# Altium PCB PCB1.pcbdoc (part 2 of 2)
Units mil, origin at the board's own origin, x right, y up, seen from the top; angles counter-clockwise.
Board outline 2401.6 x 2401.6 mil, 2 copper layers (Top Layer, Bottom Layer), stack 62.2 mil thick; 61 components, 49 nets, 315 pads, 150 vias.
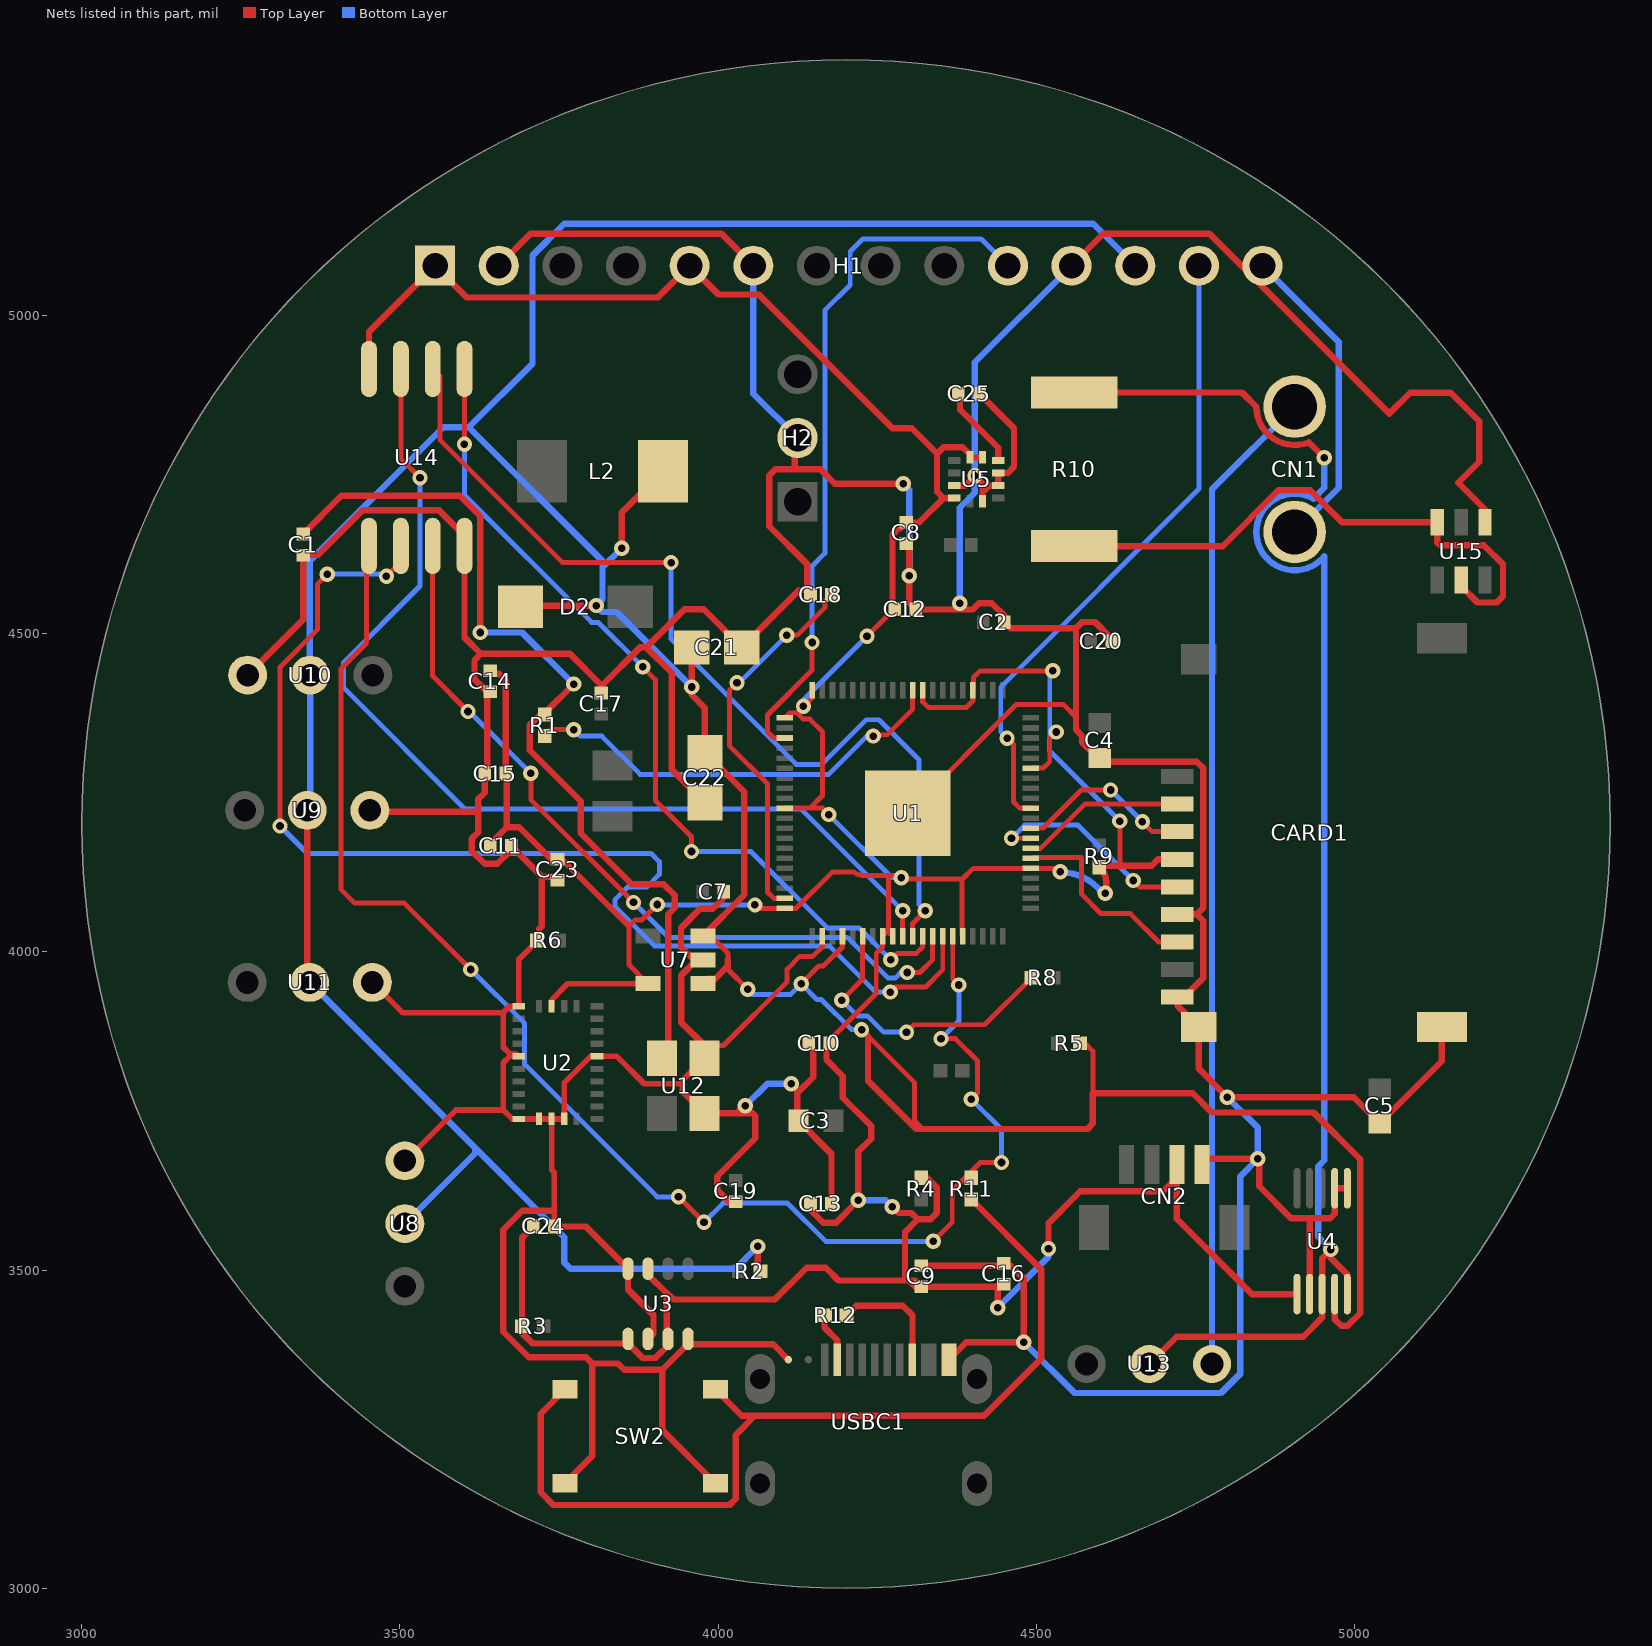
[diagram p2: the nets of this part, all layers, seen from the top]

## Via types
v1: diameter 24, hole 12, Top Layer to Bottom Layer, 150 vias

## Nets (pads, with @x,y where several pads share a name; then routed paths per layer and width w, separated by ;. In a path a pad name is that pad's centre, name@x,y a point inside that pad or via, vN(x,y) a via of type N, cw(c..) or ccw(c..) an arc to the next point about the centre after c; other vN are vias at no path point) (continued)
$1N403: H1.10 U1.43 | length 1112.8
  Top Layer w7.8: U1.43@4104.5,4335.9 4087.5,4335.9 4077.5,4345.9 4077.5,4372.1 4147.5,4442.1 v1(4147.5,4485.9)
  Bottom Layer w7.8: v1(4147.5,4485.9) 4147.5,4605.9 4167.5,4625.9 4167.5,5007.7 4207.5,5047.7 4207.5,5100.2 4227.5,5120.2 4413,5120.2 H1.10@4455.2,5078
$1N404: H1.13 U1.11 | length 1010.7
  Top Layer w7.8: v1(4453.9,4335.6) 4463.9,4325.6 4463.9,4235.6 4473.9,4225.6 U1.11@4490.9,4225.6
  Bottom Layer w7.8: v1(4453.9,4335.6) 4443.9,4345.6 4443.9,4415.6 4755.2,4727 H1.13@4755.2,5078
$1N405: CARD1.5 U1.8 | length 339.2
  Top Layer w7.8: v1(4460.9,4178.4) U1.8@4490.9,4178.4 ; v1(4652,4112.1) 4662,4102.1 CARD1.5@4721.5,4102.1
  Bottom Layer w7.8: v1(4460.9,4178.4) 4481.4,4198.9 4565.2,4198.9 v1(4652,4112.1)
$1N406: CARD1.3 U1.9 | length 282.6
  Top Layer w7.8: U1.9@4490.9,4194.2 4510.3,4194.2 4570.3,4254.2 v1(4616.5,4254.2) ; v1(4666.5,4204.2) 4682,4188.7 CARD1.3@4721.5,4188.7
  Bottom Layer w7.8: v1(4616.5,4254.2) v1(4666.5,4204.2)
$1N409: CARD1.2 U1.7 | length 259.9
  Top Layer w7.8: U1.7@4490.9,4162.7 4491.5,4162 4505.9,4162 4575.9,4232 CARD1.2@4721.5,4232
$1N413: R8.1 U1.66 | length 468.9
  Top Layer w7.8: v1(4194.1,3924.1) 4226.8,3956.8 U1.66@4226.8,4024.6 ; v1(4295.9,3873.7) 4307.5,3885.4 4418.4,3885.4 R8.1@4492.5,3959.4
  Bottom Layer w7.8: v1(4194.1,3924.1) 4218.6,3899.5 4234.4,3899.5 4260.1,3873.7 v1(4295.9,3873.7)
$1N424: R1.1 U1.30 | length 683.4
  Top Layer w7.8: R1.1@3727.6,4338.9 3737.6,4348.9 v1(3773.2,4348.9) ; v1(4243.5,4338.9) 4245.5,4341 4265.5,4341 4305.5,4381 U1.30@4305.5,4411
  Bottom Layer w7.8: v1(3773.2,4348.9) 3783.2,4338.9 3817.3,4338.9 3877.3,4278.9 4173.5,4278.9 4233.5,4338.9 v1(4243.5,4338.9)
$1N425: C1.1 R1.2 U12.1 | length 1434.9
  Top Layer w10: C1.1@3347.9,4656.4 3407.9,4716.4 3594.2,4716.4 3626.1,4684.4 v1(3626.1,4501.7) ; R1.2@3727.6,4373 R1.2@3724.2,4376.4 ; v1(3772.9,4420.6) 3728.7,4376.4 R1.2@3724.2,4376.4 ; U12.1@3911.5,3832.8 3921.5,3842.8 3921.5,4059.1 3931.5,4069.1 3931.5,4089.1 3914.2,4106.4 3864.2,4106.4 3784.2,4186.4 3784.2,4236.4 3704.2,4316.4 3704.2,4356.4 R1.2@3724.2,4376.4
  Bottom Layer w10: v1(3626.1,4501.7) 3691.9,4501.7 v1(3772.9,4420.6)
$1N433: C8.1 C9.1 C10.1 C11.1 C12.1 C13.1 C14.1 C15.1 C16.1 C23.1 C24.1 CARD1.4 CN2.2 H1.1 H1.5 R3.2 R4.2 R9.2 U1.5 U1.15 U1.24 U1.29 U1.40 U1.41 U1.50 U1.60 U1.68 U1.69 U1.76 U2.4 U3.2 U3.6 U3.8 U4.6 U5.5 U5.6 U5.10 U7.5 U14.8 | length 7842.1
  Top Layer w7.8: U7.5@3889.6,3950 3859.6,3980 3859.6,4040.3 3869.6,4050.3 3880.2,4050.3 v1(3904.3,4074.4) ; v1(4057.7,4073.7) 4063.2,4068.2 U1.60@4104.5,4068.2 4122.2,4068.2 4179.8,4125.7 4212.9,4125.7 ccw(c4226.2,4139) 4226.2,4120.2 4267,4120.2 4287.8,4120.2 v1(4287.8,4116.4) 4290,4114.3 4383.9,4114.3 ; U1.50@4104.5,4225.6 4143.9,4225.6 ; U1.41@4104.5,4367.4 4112.7,4375.6 4123.9,4375.6 ; U1.40@4148.1,4411 4148.1,4399.8 v1(4133.9,4385.6) 4123.9,4375.6 ; C10.1@4170.2,3856.4 4248.3,3934.6 4248.3,3997.6 4258.3,4007.6 U1.68@4258.3,4024.6 4264.9,4031.2 4267.5,4031.2 ; v1(4173.9,4215.6) 4163.9,4225.6 4143.9,4225.6 ; v1(4233.9,4495.6) 4273.9,4535.6 C12.1@4277.1,4538.4 ; 4267.03,4120.23 cw(c4265.9,4119.1) 4267.5,4119.1 4267.5,4031.2 ; U1.69@4274.1,4024.6 4267.5,4031.2 ; U1.29@4321.3,4411 4321.3,4392.7 4330,4384 4390,4384 4400,4394 U1.24@4400,4411 4400.9,4411.9 4400.9,4431 4410.9,4441 4450.9,4441 4451.4,4441.4 v1(4525.7,4441.4) ; U1.76@4384.3,4024.6 4382.8,4026.1 4382.8,4113.1 4383.9,4114.3 ; U1.15@4490.9,4288.6 4510.9,4288.7 4520.9,4298.7 4520.9,4335.4 v1(4530.9,4345.4) ; v1(4537.2,4125.9) 4531.9,4131.2 U1.5@4490.9,4131.2 4400.8,4131.2 4383.9,4114.3 ; 4630.9,4135.4 v1(4630.9,4205.4) ; 4123.9,4375.6 4133.9,4365.6 4143.9,4365.6 4163.9,4345.6 4163.9,4245.6 4143.9,4225.6
  Top Layer w8.9: U2.4@3738.3,3914.5 3738.3,3924.5 3763.7,3950 U7.5@3889.6,3950 ; C23.1@3747.6,4145.5 3754.4,4145.5 3859.6,4040.3
  Top Layer w9.9: C8.1@4295.8,4674.6 4315.8,4674.6 4353.9,4712.7 ; U5.10@4371.1,4712.7 4353.9,4712.7 ; U5.5@4415.4,4776.7 U5.6@4395.8,4776.7 4395.8,4780.9 4383.9,4792.7 4353.9,4792.7 4343.9,4782.7 4343.9,4722.7 4353.9,4712.7
  Top Layer w10: U14.8@3451.5,4915.7 3451.5,4974.2 H1.1@3555.2,5078 3605.2,5028 3905.2,5028 H1.5@3955.2,5078 4000.5,5032.7 4063.9,5032.7 4273.9,4822.7 4303.9,4822.7 4343.9,4782.7 ; C14.1@3641.6,4441.4 3646.2,4436.8 3656.2,4436.8 3666.2,4426.8 C15.1@3666.2,4280.1 3667.6,4278.8 3667.6,4195.5 ; C11.1@3641.7,4166.5 3641.7,4169.6 3667.6,4195.5 ; C24.1@3709.3,3568.5 3691.7,3550.9 R3.2@3691.7,3411.5 3691.7,3401.2 3708.4,3384.6 3851.1,3384.6 U3.8@3858.4,3391.8 3858.4,3384.8 3881.3,3361.8 3901.3,3361.8 3921.3,3381.8 U3.6@3921.3,3391.8 3919,3394.2 3919,3463.7 ; C23.1@3747.6,4145.5 3737.6,4145.5 3687.6,4195.5 3667.6,4195.5 ; U3.2@3889.8,3502.1 3889.8,3492.9 3919,3463.7 ; C13.1@4145,3604.5 4145,3594.5 4165,3574.5 4185,3574.5 v1(4220.2,3609.7) 4220.2,3686.4 4240.2,3706.4 4240.2,3726.4 4195.9,3770.7 4195.9,3804.6 4170.2,3830.3 C10.1@4170.2,3856.4 ; v1(4273.5,3599.7) 4283.5,3589.7 4303.5,3589.7 4313.5,3579.7 ; C12.1@4273.9,4535.6 4273.9,4655.6 4283.9,4665.6 4286.8,4665.6 C8.1@4295.8,4674.6 ; R4.2@4319,3645.1 4328.1,3645.1 4343.5,3629.7 4343.5,3589.7 4333.5,3579.7 4313.5,3579.7 ; v1(4439,3440.9) C16.1@4439,3473.7 ; C16.1@4448.9,3477.7 C16.1@4439,3473.7 ; v1(4519,3533.7) 4519,3573.7 4569,3623.7 4699,3623.7 4719,3643.7 4719,3664.4 4720.5,3666 4720.5,3580.5 4838.7,3462.3 U4.6@4909.5,3462.3 ; R9.2@4598.8,4132.9 4601.2,4135.4 4630.9,4135.4 4680.9,4135.4 4690.9,4145.4 CARD1.4@4721.5,4145.4 ; R9.2@4600.76,4131.26 cw(c4579.9,4110.4) 4609.4,4110.4 v1@4609.4,4093.6 ; 3919,3463.7 3920.2,3463.7 3930.2,3453.7 4089,3453.7 4139,3503.7 4169,3503.7 4189,3483.7 4299.4,3483.7 ; 4299.4,3483.7 4293.5,3489.7 4293.5,3559.7 4313.5,3579.7 ; 4299.4,3483.7 4309.4,3473.7 C9.1@4319,3473.7 ; 4299.4,3483.7 4309,3483.7 C9.1@4319,3473.7 ; C9.1@4319,3473.7 C16.1@4439,3473.7
  Bottom Layer w7.8: v1(3904.3,4074.4) 3905.1,4073.7 v1(4057.7,4073.7) ; v1(4133.9,4385.6) 4133.9,4395.6 v1(4233.9,4495.6) ; v1(4173.9,4215.6) 4273.1,4116.4 v1(4287.8,4116.4) ; v1(4525.7,4441.4) 4520.9,4436.7 4520.9,4335.4 ; v1(4530.9,4345.4) 4520.9,4335.4 ; v1(4630.9,4205.4) 4520.9,4315.4 4520.9,4335.4
  Bottom Layer w10: v1(4220.2,3609.7) 4263.5,3609.7 v1(4273.5,3599.7) ; v1(4439,3440.9) 4519,3520.9 v1(4519,3533.7) ; v1@4536.4,4124.8 v1@4539,4124.8 ; v1@4539,4124.9 cw(c4539,4045.3) v1@4606.65,4087.25
  other v1: 4608.3,4092.2
$1N438: R11.1 U1.75 U14.1 | length 2399.5
  Top Layer w7.8: U14.1@3451.5,4637.7 3447.7,4634 3447.7,4485.1 3407.7,4445.1 3407.7,4097.6 3428.8,4076.5 3507,4076.5 v1(3611.3,3972.2) ; v1(3937.7,3615.1) v1(3977.7,3575.1) ; v1(4337.7,3545.1) 4367.7,3575.1 4367.7,3625.1 4411.6,3669 v1(4445,3669) ; v1(4350.1,3863.5) 4372.7,3863.5 4407.7,3828.4 4407.7,3778.4 v1(4397.7,3768.4) ; U1.75@4368.5,4024.6 4368.5,3957.4 v1(4378,3947.9)
  Bottom Layer w7.8: v1(3611.3,3972.2) 3695.9,3887.6 3695.9,3823.2 3904,3615.1 v1(3937.7,3615.1) ; v1(3977.7,3575.1) 4007.7,3605.1 4109,3605.1 4169,3545.1 v1(4337.7,3545.1) ; v1(4350.1,3863.5) 4378,3891.3 v1(4378,3947.9) ; v1(4397.7,3768.4) 4445,3721.1 v1(4445,3669)
$1N439: R11.2 SW2.1 SW2.2 | length 1501.4
  Top Layer w10: SW2.1@3759.4,3312.7 3721,3274.3 3721,3151 3741,3131 4017.7,3131 4027.7,3141 4027.7,3241 4057.7,3271 ; SW2.2@3995.6,3312.7 4037.2,3271 4417.7,3271 4507.7,3361 4507.7,3501 R11.2@4397.7,3611
$1N444: C18.1 U1.59 | length 601.4
  Top Layer w7.8: v1(4029.6,4422.7) 4017.5,4410.6 4017.5,4323.9 4077.5,4263.9 4077.5,4093.9 4087.5,4083.9 U1.59@4104.5,4083.9 ; v1(4107.5,4497.4) 4124.2,4497.4 4167.5,4540.6 4167.5,4550.6 C18.1@4178,4561.1
  Bottom Layer w7.8: v1(4029.6,4422.7) 4032.9,4422.7 v1(4107.5,4497.4)
$1N449: U1.74 U14.2 | length 1951.9
  Top Layer w7.8: v1(3311.5,4197.7) 3311.5,4447.3 3370.2,4506 3370.2,4577.3 v1(3386,4593.2) ; v1(3478.8,4590.1) 3501.5,4612.8 U14.2@3501.5,4637.7 ; v1(4270.2,3936.7) 4278.1,3944.5 4325.8,3944.5 4352.8,3971.6 U1.74@4352.8,4024.6
  Bottom Layer w7.8: v1(3311.5,4197.7) 3354.7,4154.5 3894.7,4154.5 3907.6,4141.6 3907.6,4121.6 3887.6,4101.6 3857.6,4101.6 3837.6,4081.6 3837.6,4071.6 3900.3,4008.9 4175.5,4008.9 4247.7,3936.7 v1(4270.2,3936.7) ; v1(3386,4593.2) 3475.7,4593.2 v1(3478.8,4590.1)
$1N450: U1.73 U14.3 | length 1260.1
  Top Layer w7.8: U14.3@3551.5,4637.7 3551.5,4433.2 v1(3607,4377.6) ; v1(3705.7,4280.5) 3705.7,4238.9 v1(3867,4077.6) ; v1(4297,3967.6) 4317,3967.6 4337,3987.6 U1.73@4337,4024.6
  Bottom Layer w7.8: v1(3607,4377.6) 3608.7,4377.6 v1(3705.7,4280.5) ; v1(3867,4077.6) 3922,4022.7 4203,4022.7 4267,3958.6 4278.1,3958.6 4287,3967.6 v1(4297,3967.6)
$1N451: U1.72 U14.5 | length 1370.5
  Top Layer w7.8: v1(3601.3,4797.6) U14.5@3601.3,4915.5 ; v1(3881.3,4447.6) 3901.3,4427.6 3901.3,4237.6 3958,4180.9 v1(3958,4157.6) ; v1(4271.3,3987.6) 4281.3,3997.6 4311.3,3997.6 4321.3,4007.6 U1.72@4321.3,4024.6
  Bottom Layer w7.8: v1(3601.3,4797.6) 3601.3,4717.6 3801.3,4517.6 3811.3,4517.6 v1(3881.3,4447.6) ; v1(3958,4157.6) 4051.3,4157.6 4171.3,4037.6 4221.3,4037.6 v1(4271.3,3987.6)
$1N452: U1.71 U14.6 | length 1494.9
  Top Layer w7.8: U14.6@3551.5,4915.7 3562.6,4904.6 3562.6,4804.6 3755.7,4611.5 v1(3926,4611.5) ; U1.71@4305.5,4024.6 4305.5,4044.6 v1(4325.5,4064.6)
  Bottom Layer w7.8: v1(3926,4611.5) 3926,4491.2 4122.6,4294.6 4162.6,4294.6 4232.6,4364.6 4252.6,4364.6 4315.5,4301.6 4315.5,4074.6 v1(4325.5,4064.6)
$1N453: U1.70 U14.7 | length 1626.5
  Top Layer w7.8: U14.7@3501.5,4915.7 3501.5,4774.6 v1(3531.5,4744.6) ; U1.70@4289.8,4024.6 v1(4289.8,4064.6)
  Bottom Layer w7.8: v1(3531.5,4744.6) 3531.5,4574.6 3411.5,4454.6 3411.5,4414.6 3601.5,4224.6 4129.8,4224.6 v1(4289.8,4064.6)
$1N456: C25.1 U5.4 | length 131.1
  Top Layer w9.9: C25.1@4377.5,4877 4380,4874.5 4380,4851.8 4440,4791.8 U5.4@4440,4771.8
$1N460: CARD1.7 U1.6 | length 319.9
  Top Layer w7.8: U1.6@4490.9,4146.9 4494.8,4146.9 4496.1,4148.2 4570.9,4148.2 4570.9,4090.5 4601.5,4060 4647.5,4060 4692,4015.5 CARD1.7@4721.5,4015.5
$1N462: R10.1 U4.8 U4.10 U13.2 | length 2388.2
  Top Layer w10: R10.1@4559.5,4878.8 4823,4878.8 4845.4,4856.4 ccw(c4905.6,4856.4) 4927.76,4800.43 ; U13.2@4677.2,3352.5 4720.2,3395.4 4918.9,3395.4 4948.9,3425.4 U4.8@4948.9,3462.3 4948.9,3518.8 v1(4962.4,3532.3) 4962.4,3518.9 4988.3,3493 U4.10@4988.3,3462.3 ; 4927.7,4800.4 v1(4952.2,4776)
  Bottom Layer w10: 4935.3,4711.9 4952.2,4728.8 v1(4952.2,4776) ; 4935.34,4711.94 ccw(c4905.6,4659.6) 4845.4,4659.6 ccw(c4905.6,4659.6) 4952.19,4621.47 ; 4952.2,4621.5 4952.2,3672.4 4942.5,3662.7 4942.5,3552.2 v1(4962.4,3532.3)
$1N464: CN1.2 U13.1 | length 1557.7
  Bottom Layer w10: U13.1@4775.7,3352.5 4775.7,4726.5 CN1.2@4905.6,4856.4
$1N465: C1.2 C2.2 C3.2 C4.2 C5.2 C7.2 C8.2 C9.2 C10.2 C11.2 C12.2 C13.2 C14.2 C15.2 C16.2 C17.2 C18.2 C19.2 C20.2 C21.2 C22.2 C23.2 C24.2 C25.2 CARD1.6 CARD1.9 CARD1.10 CARD1.11 CN1.1 CN2.1 H1.2 H1.6 H1.11 H1.14 H2.2 R6.2 SW2.3 SW2.4 U1.62 U1.81 U2.6 U2.10 U2.15 U2.16 U2.17 U2.18 U2.25 U3.1 U3.5 U3.7 U4.1 U4.2 U4.7 U5.2 U5.3 U5.9 U5.12 U7.2 U8.3 U9.3 U10.3 U11.3 U12.3 U12.4 U14.4 U15.1 USBC1.A1B12 USBC1.B1A12 | length 14395.4
  Top Layer w7.8: U12.4@3978.4,3852.8 4008.4,3852.8 4108.4,3952.8 4108.4,3972.8 4128.4,3992.8 4148.4,3992.8 4163.8,4008.2 U1.62@4163.8,4024.6 ; U1.81@4297.7,4217.8 4468.7,4388.8 4542.1,4388.8 4562.1,4368.8
  Top Layer w8.9: U11.3@3456.8,3951.8 3504.1,3904.5 3662.3,3904.5 ; U8.3@3507.8,3671.4 3588.1,3751.6 3662.3,3751.6 ; 3718.8,4036.2 3718.8,4020 3686.6,3987.8 U2.6@3686.6,3914.5 3672.3,3914.5 3662.3,3904.5 ; C24.2@3742.4,3568.5 3742.4,3653.3 3738.3,3657.4 U2.17@3738.3,3737.4 ; U12.4@3978.4,3832.8 3943.9,3798.3 3943.9,3792.8 3883.9,3792.8 3840.9,3835.8 U2.25@3809.6,3835.8 3799.6,3835.8 3758,3794.1 U2.18@3758,3737.4 U2.17@3738.3,3737.4 ; 3662.3,3751.6 3662.3,3825.8 3672.3,3835.8 U2.10@3686.6,3835.8 3682.3,3840 3672.3,3840 3662.3,3850 3662.3,3904.5 ; 3662.3,3751.6 3676.6,3737.4 U2.15@3686.6,3737.4 U2.16@3718.6,3737.4 U2.17@3738.3,3737.4
  Top Layer w9.9: U5.9@4371.1,4732.4 4388,4732.4 v1(4403.3,4747.7) 4415.4,4735.5 4415.4,4722.1 ; v1@4379.7,4537.8 v1(4379.7,4547.8) ; C25.2@4410.6,4877 4464.8,4822.8 4464.8,4762.1 4454.8,4752.1 U5.3@4440,4752.1 U5.2@4440,4732.4 4425.7,4732.4 4415.4,4722.1 ; U5.12@4415.4,4707.8 4415.4,4722.1
  Top Layer w10: U10.3@3260.7,4434.8 3347.9,4522 C1.2@3347.9,4623.3 3348.4,4623.9 3371.5,4623.9 3441.5,4693.8 3561.5,4693.8 3601.5,4653.8 U14.4@3601.5,4633.9 ; U9.3@3452.8,4222.1 3454.7,4220.1 3623.1,4220.1 ; U14.4@3601.5,4637.7 3601.5,4493.9 3627.1,4468.2 ; C14.2@3641.6,4408.3 C14.2@3637.1,4408.2 ; H1.2@3655.2,5078 3705.2,5128 4005.2,5128 H1.6@4055.2,5078 ; C11.2@3674.8,4166.5 C11.2@3673.1,4158.1 ; 3718.8,4036.2 3723.1,4040.5 3723.1,4118.1 ; C24.2@3742.4,3568.5 3792,3568.5 U3.1@3858.4,3502.1 3858.4,3469.4 3898.4,3429.4 3898.4,3400.4 U3.7@3889.8,3391.8 ; 3742.4,3593.3 3692.4,3593.3 3662.4,3563.3 3662.4,3403.3 3702.4,3363.3 3792.4,3363.3 3802.4,3353.3 ; C23.2@3747.6,4112.4 3742,4118.1 3723.1,4118.1 ; SW2.3@3759.4,3165 3802.4,3208 3802.4,3353.3 ; C17.2@3816.6,4406.6 3817.1,4418.2 ; 3943.9,3792.8 3943.9,3780.7 U12.3@3978.4,3746.2 4028.4,3746.2 ; U3.5@3952.8,3391.8 U3.5@3952.4,3383.3 ; U12.4@3978.4,3832.8 3978.4,3852.8 3941.7,3889.6 3941.7,3962.8 3966.2,3987.4 U7.2@3976.2,3987.4 3961.5,3987.4 3941.5,4007.4 3941.5,4037.4 3971.5,4067.4 3991.5,4067.4 4008.9,4084.7 C7.2@4008.9,4094.7 ; C22.2@3979.1,4234.4 3927.1,4286.4 3927.1,4438.2 3887.1,4478.2 ; SW2.4@3995.6,3165 3912.4,3248.3 3912.4,3343.3 ; C19.2@4027.6,3607.6 4017,3607.6 3998.4,3626.2 3998.4,3647.5 4058.3,3707.3 4058.3,3742.3 4054.4,3746.2 4028.4,3746.2 ; v1(4042.4,3758) 4040.2,3758 4028.4,3746.2 ; USBC1.A1B12@4110.3,3359.3 4086.4,3383.3 U3.5@3952.4,3383.3 ; v1(4114.8,3792.9) 4124.3,3783.4 4124.3,3778.2 ; H2.2@4124.8,4807.4 4120.2,4802.8 4120.2,4758.4 ; C10.2@4137.1,3856.4 4149.3,3844.2 4149.3,3803.2 4124.3,3778.2 ; C18.2@4145,4561.1 C18.2@4140.2,4568.4 ; C13.2@4178,3604.5 4178,3682.4 C3.2@4126.1,3734.4 4124.3,3736.2 4124.3,3778.2 ; v1(4290.6,4735.5) 4183.1,4735.5 4160.2,4758.4 4120.2,4758.4 ; C8.2@4295.8,4641.5 4300.2,4637.1 v1(4300.2,4590.8) 4300.2,4548.4 C12.2@4310.2,4538.4 4310.8,4537.8 4399.7,4537.8 4409.7,4547.8 4429.7,4547.8 4449.7,4527.8 C2.2@4449.7,4517.8 4459.3,4508.2 4562.1,4508.2 ; C9.2@4319,3506.8 4459.9,3506.8 4479.9,3486.8 v1(4479.9,3386.8) 4389.8,3386.8 USBC1.B1A12@4362.3,3359.3 ; C16.2@4448.9,3510.8 C16.2@4449.9,3506.8 ; H1.11@4555.2,5078 4605.2,5128 4771.8,5128 5054.2,4845.6 5087.1,4878.5 5150.8,4878.5 5195.8,4833.5 5195.8,4769.8 5162.9,4736.9 5205.2,4694.6 5205.2,4675.4 U15.1@5204.7,4674.9 ; C4.2@4599.8,4304.6 4605.6,4298.8 4752.1,4298.8 4762.1,4288.8 4762.1,4068.8 4752.1,4058.8 ; C4.2@4612.1,4298.8 4602.1,4298.8 4572.1,4328.8 4572.1,4338.8 4562.1,4348.8 4562.1,4508.2 ; C20.2@4618.5,4488.2 4618.5,4491.8 4592.1,4518.2 4572.1,4518.2 4562.1,4508.2 ; CARD1.6@4721.5,4058.8 4752.1,4058.8 ; CN2.1@4759.9,3666 4768.7,3674.7 v1(4847.7,3674.7) 4849.9,3672.5 4849.9,3631.6 4899.9,3581.6 4961.7,3581.6 4968.6,3588.5 U4.2@4968.6,3628.5 U4.1@4988.3,3628.5 ; U4.7@4929.2,3462.3 4929.2,3579.1 4931.7,3581.6 ; CARD1.11@5136.9,3881.6 5136.9,3827.9 5039.5,3730.4 4998.3,3771.6 v1(4799.9,3771.6) 4755,3816.6 CARD1.10@4755,3881.6 4721.5,3915.1 CARD1.9@4721.5,3928.9 4732.2,3928.9 4762.1,3958.8 4762.1,4048.8 4752.1,4058.8 ; 3627.1,4468.2 3767.1,4468.2 3817.1,4418.2 ; 3627.1,4468.2 3617.1,4458.2 3617.1,4428.2 C14.2@3637.1,4408.2 ; C14.2@3637.1,4408.2 3637.1,4284.1 C15.2@3633.1,4280.1 3633.1,4250.1 3623.1,4240.1 3623.1,4188.1 3613.1,4178.1 3613.1,4158.1 3633.1,4138.1 3653.1,4138.1 C11.2@3673.1,4158.1 ; C11.2@3673.1,4158.1 3683.1,4158.1 3723.1,4118.1 ; 3802.4,3353.3 3842.4,3353.3 3852.4,3343.3 3912.4,3343.3 ; 3817.1,4418.2 3877.1,4478.2 3887.1,4478.2 ; 3887.1,4478.2 3947.1,4538.2 3977.1,4538.2 C21.2@4037.1,4478.2 4127.3,4568.4 C18.2@4140.2,4568.4 ; 3912.4,3343.3 U3.5@3952.4,3383.3 ; 4120.2,4758.4 4090.2,4758.4 4080.2,4748.4 4080.2,4668.4 4140.2,4608.4 C18.2@4140.2,4568.4
  Bottom Layer w9.9: v1(4379.7,4547.8) 4379.7,4697.8 4403.3,4721.4 v1(4403.3,4747.7)
  Bottom Layer w10: v1(4042.4,3758) 4077.4,3792.9 v1(4114.8,3792.9) ; H1.6@4055.2,5078 4055.2,4876.9 H2.2@4124.8,4807.4 ; v1(4290.6,4735.5) 4300.2,4725.9 v1(4300.2,4590.8) ; v1(4403.3,4747.7) 4403.3,4926 H1.11@4555.2,5078 ; v1(4479.9,3386.8) 4559.9,3306.8 4789.9,3306.8 4819.9,3336.8 4819.9,3647 v1(4847.7,3674.7) 4847.7,3723.9 v1(4799.9,3771.6) ; H1.14@4855.2,5078 4975.2,4958 4975.2,4729.2 CN1.1@4905.6,4659.6
$1N470: R10.2 U15.3 U15.5 | length 916.8
  Top Layer w10: R10.2@4559.5,4637.4 4792.5,4637.4 4880,4724.9 4930,4724.9 4980,4674.9 U15.3@5129.9,4674.9 5129.9,4642.9 5134.1,4638.8 5202.9,4638.8 5232.9,4608.8 5232.9,4558.8 5222.9,4548.8 5192.9,4548.8 5167.3,4574.4 U15.5@5167.3,4584.4
$1N471: C21.1 C22.1 D2.1 H1.12 L2.2 R2.2 R5.1 U1.64 U4.9 U7.1 U7.3 U8.2 U9.2 U10.2 U11.2 | length 6928.5
  Top Layer w7.8: U7.3@3976.2,4024.8 3988.1,4024.8 4015.3,3997.6 4015.3,3987.6 ; 4015.3,3977.6 4015.3,3972.2 v1(4046.4,3941.2) ; v1(4130.3,3949.7) 4158.2,3977.6 4165.3,3977.6 4195.3,4007.6 U1.64@4195.3,4024.6 ; v1(4225.3,3877.6) 4308.6,3794.3 4308.6,3734.3 4321.3,3721.6 4321.6,3721.3 ; R5.1@4568.3,3856.4 4576.2,3856.4 4588.6,3844 4588.6,3777.6
  Top Layer w10: U9.2@3354.4,4222.1 3354.4,3955.8 U11.2@3358.4,3951.8 ; D2.1@3689.2,4541.9 3691.2,4543.9 v1(3808.3,4543.9) ; v1(3848.3,4633.9) 3848.3,4690.1 L2.2@3913.1,4754.8 ; C21.1@3958.3,4478.2 v1(3958.3,4416) 3958.3,4403.9 3979.1,4383.1 C22.1@3979.1,4313.1 4040.9,4251.3 4040.9,4089.5 U7.3@3976.2,4024.8 ; U7.1@3976.2,3950 3983.8,3957.6 3995.3,3957.6 4015.3,3977.6 4015.3,3987.6 ; v1(4062.3,3537.2) 4062.3,3502.6 R2.2@4066.7,3498.2 ; 4235.3,3867.6 4235.3,3797.6 4311.3,3721.6 4321.3,3721.6 4580.1,3721.6 4588.6,3730.2 4588.6,3777.6 4745.3,3777.6 4775.3,3747.6 4935.3,3747.6 5008.6,3674.3 5008.6,3432.3 4988.6,3412.3 4978.6,3412.3 4968.6,3422.3 U4.9@4968.6,3462.3
  Bottom Layer w7.8: v1(4046.4,3941.2) 4054.8,3932.7 4113.4,3932.7 v1(4130.3,3949.7) 4155.2,3924.8 4162.3,3924.8 4209.6,3877.6 v1(4225.3,3877.6)
  Bottom Layer w10: U9.2@3354.4,4222.1 3359.1,4226.7 U10.2@3359.1,4434.8 3358.3,4435.6 3358.3,4613.9 3568.3,4823.9 3608.3,4823.9 ; U11.2@3358.4,3951.8 3581.1,3729.1 3758.4,3551.8 3758.4,3511.8 3768.4,3501.8 4026.9,3501.8 v1(4062.3,3537.2) ; U8.2@3507.8,3573 3618.4,3683.5 3618.4,3691.8 ; v1(3848.3,4633.9) 3818.3,4603.9 ; v1(3958.3,4416) 3840.5,4533.9 3818.3,4533.9 v1(3808.3,4543.9) 3818.3,4553.9 3818.3,4603.9 ; H1.12@4655.2,5078 4589.3,5143.9 3758.3,5143.9 3708.3,5093.9 3708.3,4923.9 3608.3,4823.9 ; 3608.3,4823.9 3818.3,4613.9 3818.3,4603.9
$1N472: R12.2 USBC1.B5 | length 185.3
  Top Layer w10: R12.2@4201.8,3429.1 4216.7,3443.9 4290.1,3443.9 4305.2,3428.9 USBC1.B5@4305.2,3359.3
$1N473: R12.1 USBC1.A5 | length 78.3
  Top Layer w10: R12.1@4167.7,3429.1 4167.1,3428.4 4167.1,3409.9 4187.1,3389.9 USBC1.A5@4187.1,3359.3
pads on no net: CARD1.1 CARD1.8 CARD1.12 CARD1.13 CN2.0 U1.3 U1.4 U1.12 U1.13 U1.14 U1.16 U1.17 U1.18 U1.19 U1.20 U1.21 U1.22 U1.23 U1.25 U1.26 U1.27 U1.28 U1.35 U1.36 U1.37 U1.38 U1.39 U1.42 U1.47 U1.48 U1.49 U1.52 U1.53 U1.54 U1.55 U1.56 U1.57 U1.58 U2.1 U2.2 U2.3 U2.5 U2.7 U2.8 U2.9 U2.12 U2.13 U2.14 U2.21 U2.22 U2.23 U2.24 U2.26 U2.27 U2.28 U4.3 U5.7 U5.8 U7.4 U13.3 USBC1.1 USBC1.2 USBC1.3 USBC1.4 USBC1.A8 USBC1.B6 USBC1.B7 USBC1.B8

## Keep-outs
Board Outline Layer:
  region: 3348,4782.3 3347.6,4775.5 3346.5,4768.7 3344.5,4762.1 3341.9,4755.8 3338.5,4749.8 3334.5,4744.3 3329.8,4739.3 3324.7,4734.8 3319,4730.9 3312.9,4727.7 3306.5,4725.2 3299.9,4723.5 3293.1,4722.5 3286.3,4722.3 3279.4,4722.9 3272.7,4724.2 3266.2,4726.4 3260,4729.2 3254.1,4732.7 3248.7,4736.9 3243.8,4741.7 3239.4,4747 3235.7,4752.8 3232.7,4758.9 3230.4,4765.4 3228.8,4772.1 3228,4778.9 3228,4785.7 3228.8,4792.5 3230.4,4799.2 3232.7,4805.7 3235.7,4811.8 3239.4,4817.6 3243.8,4822.9 3248.7,4827.7 3254.1,4831.9 3260,4835.4 3266.2,4838.3 3272.7,4840.4 3279.4,4841.7 3286.3,4842.3 3293.1,4842.1 3299.9,4841.2 3306.5,4839.4 3312.9,4836.9 3319,4833.7 3324.7,4829.9 3329.8,4825.4 3334.5,4820.3 3338.5,4814.8 3341.9,4808.8 3344.5,4802.5 3346.5,4795.9 3347.6,4789.2
  region: 3348,4782.3 3347.6,4775.5 3346.5,4768.7 3344.5,4762.1 3341.9,4755.8 3338.5,4749.8 3334.5,4744.3 3329.8,4739.3 3324.7,4734.8 3319,4730.9 3312.9,4727.7 3306.5,4725.2 3299.9,4723.5 3293.1,4722.5 3286.3,4722.3 3279.4,4722.9 3272.7,4724.2 3266.2,4726.4 3260,4729.2 3254.1,4732.7 3248.7,4736.9 3243.8,4741.7 3239.4,4747 3235.7,4752.8 3232.7,4758.9 3230.4,4765.4 3228.8,4772.1 3228,4778.9 3228,4785.7 3228.8,4792.5 3230.4,4799.2 3232.7,4805.7 3235.7,4811.8 3239.4,4817.6 3243.8,4822.9 3248.7,4827.7 3254.1,4831.9 3260,4835.4 3266.2,4838.3 3272.7,4840.4 3279.4,4841.7 3286.3,4842.3 3293.1,4842.1 3299.9,4841.2 3306.5,4839.4 3312.9,4836.9 3319,4833.7 3324.7,4829.9 3329.8,4825.4 3334.5,4820.3 3338.5,4814.8 3341.9,4808.8 3344.5,4802.5 3346.5,4795.9 3347.6,4789.2
  region: 5179,4801.7 5178.6,4794.8 5177.4,4788.1 5175.5,4781.5 5172.8,4775.2 5169.4,4769.2 5165.4,4763.7 5160.8,4758.6 5155.6,4754.1 5149.9,4750.2 5143.9,4747 5137.5,4744.6 5130.9,4742.8 5124.1,4741.8 5117.2,4741.6 5110.4,4742.2 5103.7,4743.6 5097.2,4745.7 5090.9,4748.6 5085,4752.1 5079.6,4756.3 5074.7,4761.1 5070.4,4766.4 5066.7,4772.1 5063.6,4778.3 5061.3,4784.7 5059.8,4791.4 5059,4798.2 5059,4805.1 5059.8,4811.9 5061.3,4818.6 5063.6,4825 5066.7,4831.2 5070.4,4837 5074.7,4842.3 5079.6,4847 5085,4851.2 5090.9,4854.8 5097.2,4857.6 5103.7,4859.7 5110.4,4861.1 5117.2,4861.7 5124.1,4861.5 5130.9,4860.5 5137.5,4858.8 5143.9,4856.3 5149.9,4853.1 5155.6,4849.2 5160.8,4844.7 5165.4,4839.7 5169.4,4834.1 5172.8,4828.2 5175.5,4821.8 5177.4,4815.3 5178.6,4808.5
  region: 5179,4801.7 5178.6,4794.8 5177.4,4788.1 5175.5,4781.5 5172.8,4775.2 5169.4,4769.2 5165.4,4763.7 5160.8,4758.6 5155.6,4754.1 5149.9,4750.2 5143.9,4747 5137.5,4744.6 5130.9,4742.8 5124.1,4741.8 5117.2,4741.6 5110.4,4742.2 5103.7,4743.6 5097.2,4745.7 5090.9,4748.6 5085,4752.1 5079.6,4756.3 5074.7,4761.1 5070.4,4766.4 5066.7,4772.1 5063.6,4778.3 5061.3,4784.7 5059.8,4791.4 5059,4798.2 5059,4805.1 5059.8,4811.9 5061.3,4818.6 5063.6,4825 5066.7,4831.2 5070.4,4837 5074.7,4842.3 5079.6,4847 5085,4851.2 5090.9,4854.8 5097.2,4857.6 5103.7,4859.7 5110.4,4861.1 5117.2,4861.7 5124.1,4861.5 5130.9,4860.5 5137.5,4858.8 5143.9,4856.3 5149.9,4853.1 5155.6,4849.2 5160.8,4844.7 5165.4,4839.7 5169.4,4834.1 5172.8,4828.2 5175.5,4821.8 5177.4,4815.3 5178.6,4808.5
  region: 3356.3,3622.1 3355.9,3615.3 3354.7,3608.5 3352.8,3601.9 3350.1,3595.6 3346.7,3589.7 3342.7,3584.1 3338.1,3579.1 3332.9,3574.6 3327.2,3570.7 3321.2,3567.5 3314.8,3565 3308.1,3563.3 3301.4,3562.3 3294.5,3562.1 3287.7,3562.7 3281,3564.1 3274.4,3566.2 3268.2,3569 3262.3,3572.6 3256.9,3576.7 3252,3581.5 3247.6,3586.8 3243.9,3592.6 3240.9,3598.7 3238.6,3605.2 3237.1,3611.9 3236.3,3618.7 3236.3,3625.5 3237.1,3632.4 3238.6,3639 3240.9,3645.5 3243.9,3651.6 3247.6,3657.4 3252,3662.7 3256.9,3667.5 3262.3,3671.7 3268.2,3675.2 3274.4,3678.1 3281,3680.2 3287.7,3681.6 3294.5,3682.1 3301.4,3681.9 3308.1,3681 3314.8,3679.2 3321.2,3676.7 3327.2,3673.5 3332.9,3669.7 3338.1,3665.2 3342.7,3660.1 3346.7,3654.6 3350.1,3648.6 3352.8,3642.3 3354.7,3635.7 3355.9,3629
  region: 3356.3,3622.1 3355.9,3615.3 3354.7,3608.5 3352.8,3601.9 3350.1,3595.6 3346.7,3589.7 3342.7,3584.1 3338.1,3579.1 3332.9,3574.6 3327.2,3570.7 3321.2,3567.5 3314.8,3565 3308.1,3563.3 3301.4,3562.3 3294.5,3562.1 3287.7,3562.7 3281,3564.1 3274.4,3566.2 3268.2,3569 3262.3,3572.6 3256.9,3576.7 3252,3581.5 3247.6,3586.8 3243.9,3592.6 3240.9,3598.7 3238.6,3605.2 3237.1,3611.9 3236.3,3618.7 3236.3,3625.5 3237.1,3632.4 3238.6,3639 3240.9,3645.5 3243.9,3651.6 3247.6,3657.4 3252,3662.7 3256.9,3667.5 3262.3,3671.7 3268.2,3675.2 3274.4,3678.1 3281,3680.2 3287.7,3681.6 3294.5,3682.1 3301.4,3681.9 3308.1,3681 3314.8,3679.2 3321.2,3676.7 3327.2,3673.5 3332.9,3669.7 3338.1,3665.2 3342.7,3660.1 3346.7,3654.6 3350.1,3648.6 3352.8,3642.3 3354.7,3635.7 3355.9,3629
  region: 5187.2,3641.5 5186.8,3634.6 5185.6,3627.9 5183.7,3621.3 5181,3615 5177.7,3609 5173.6,3603.5 5169,3598.4 5163.8,3593.9 5158.2,3590.1 5152.1,3586.9 5145.7,3584.4 5139.1,3582.6 5132.3,3581.6 5125.4,3581.5 5118.6,3582 5111.9,3583.4 5105.4,3585.5 5099.1,3588.4 5093.3,3591.9 5087.8,3596.1 5082.9,3600.9 5078.6,3606.2 5074.9,3611.9 5071.9,3618.1 5069.6,3624.6 5068,3631.2 5067.2,3638 5067.2,3644.9 5068,3651.7 5069.6,3658.4 5071.9,3664.8 5074.9,3671 5078.6,3676.8 5082.9,3682.1 5087.8,3686.8 5093.3,3691 5099.1,3694.6 5105.4,3697.4 5111.9,3699.5 5118.6,3700.9 5125.4,3701.5 5132.3,3701.3 5139.1,3700.3 5145.7,3698.6 5152.1,3696.1 5158.2,3692.9 5163.8,3689 5169,3684.5 5173.6,3679.5 5177.7,3673.9 5181,3668 5183.7,3661.6 5185.6,3655.1 5186.8,3648.3
  region: 5187.2,3641.5 5186.8,3634.6 5185.6,3627.9 5183.7,3621.3 5181,3615 5177.7,3609 5173.6,3603.5 5169,3598.4 5163.8,3593.9 5158.2,3590.1 5152.1,3586.9 5145.7,3584.4 5139.1,3582.6 5132.3,3581.6 5125.4,3581.5 5118.6,3582 5111.9,3583.4 5105.4,3585.5 5099.1,3588.4 5093.3,3591.9 5087.8,3596.1 5082.9,3600.9 5078.6,3606.2 5074.9,3611.9 5071.9,3618.1 5069.6,3624.6 5068,3631.2 5067.2,3638 5067.2,3644.9 5068,3651.7 5069.6,3658.4 5071.9,3664.8 5074.9,3671 5078.6,3676.8 5082.9,3682.1 5087.8,3686.8 5093.3,3691 5099.1,3694.6 5105.4,3697.4 5111.9,3699.5 5118.6,3700.9 5125.4,3701.5 5132.3,3701.3 5139.1,3700.3 5145.7,3698.6 5152.1,3696.1 5158.2,3692.9 5163.8,3689 5169,3684.5 5173.6,3679.5 5177.7,3673.9 5181,3668 5183.7,3661.6 5185.6,3655.1 5186.8,3648.3
  lines w0.1: 3228,4778.9 3228.8,4772.1 3230.4,4765.4 3232.7,4758.9 3235.7,4752.8 3239.4,4747 3243.8,4741.7 3248.7,4736.9 3254.1,4732.7 3260,4729.2 3266.2,4726.4 3272.7,4724.2 3279.4,4722.9 3286.3,4722.3 3293.1,4722.5 3299.9,4723.5 3306.5,4725.2 3312.9,4727.7 3319,4730.9 3324.7,4734.8 3329.8,4739.3 3334.5,4744.3 3338.5,4749.8 3341.9,4755.8 3344.5,4762.1 3346.5,4768.7 3347.6,4775.5 3348,4782.3 3347.6,4789.2 3346.5,4795.9 3344.5,4802.5 3341.9,4808.8 3338.5,4814.8 3334.5,4820.3 3329.8,4825.4 3324.7,4829.9 3319,4833.7 3312.9,4836.9 3306.5,4839.4 3299.9,4841.2 3293.1,4842.1 3286.3,4842.3 3279.4,4841.7 3272.7,4840.4 3266.2,4838.3 3260,4835.4 3254.1,4831.9 3248.7,4827.7 3243.8,4822.9 3239.4,4817.6 3235.7,4811.8 3232.7,4805.7 3230.4,4799.2 3228.8,4792.5 3228,4785.7 3228,4778.9 ; 3236.3,3618.7 3237.1,3611.9 3238.6,3605.2 3240.9,3598.7 3243.9,3592.6 3247.6,3586.8 3252,3581.5 3256.9,3576.7 3262.3,3572.6 3268.2,3569 3274.4,3566.2 3281,3564.1 3287.7,3562.7 3294.5,3562.1 3301.4,3562.3 3308.1,3563.3 3314.8,3565 3321.2,3567.5 3327.2,3570.7 3332.9,3574.6 3338.1,3579.1 3342.7,3584.1 3346.7,3589.7 3350.1,3595.6 3352.8,3601.9 3354.7,3608.5 3355.9,3615.3 3356.3,3622.1 3355.9,3629 3354.7,3635.7 3352.8,3642.3 3350.1,3648.6 3346.7,3654.6 3342.7,3660.1 3338.1,3665.2 3332.9,3669.7 3327.2,3673.5 3321.2,3676.7 3314.8,3679.2 3308.1,3681 3301.4,3681.9 3294.5,3682.1 3287.7,3681.6 3281,3680.2 3274.4,3678.1 3268.2,3675.2 3262.3,3671.7 3256.9,3667.5 3252,3662.7 3247.6,3657.4 3243.9,3651.6 3240.9,3645.5 3238.6,3639 3237.1,3632.4 3236.3,3625.5 3236.3,3618.7 ; 5059,4798.2 5059.8,4791.4 5061.3,4784.7 5063.6,4778.3 5066.7,4772.1 5070.4,4766.4 5074.7,4761.1 5079.6,4756.3 5085,4752.1 5090.9,4748.6 5097.2,4745.7 5103.7,4743.6 5110.4,4742.2 5117.2,4741.6 5124.1,4741.8 5130.9,4742.8 5137.5,4744.6 5143.9,4747 5149.9,4750.2 5155.6,4754.1 5160.8,4758.6 5165.4,4763.7 5169.4,4769.2 5172.8,4775.2 5175.5,4781.5 5177.4,4788.1 5178.6,4794.8 5179,4801.7 5178.6,4808.5 5177.4,4815.3 5175.5,4821.8 5172.8,4828.2 5169.4,4834.1 5165.4,4839.7 5160.8,4844.7 5155.6,4849.2 5149.9,4853.1 5143.9,4856.3 5137.5,4858.8 5130.9,4860.5 5124.1,4861.5 5117.2,4861.7 5110.4,4861.1 5103.7,4859.7 5097.2,4857.6 5090.9,4854.8 5085,4851.2 5079.6,4847 5074.7,4842.3 5070.4,4837 5066.7,4831.2 5063.6,4825 5061.3,4818.6 5059.8,4811.9 5059,4805.1 5059,4798.2 ; 5067.2,3638 5068,3631.2 5069.6,3624.6 5071.9,3618.1 5074.9,3611.9 5078.6,3606.2 5082.9,3600.9 5087.8,3596.1 5093.3,3591.9 5099.1,3588.4 5105.4,3585.5 5111.9,3583.4 5118.6,3582 5125.4,3581.5 5132.3,3581.6 5139.1,3582.6 5145.7,3584.4 5152.1,3586.9 5158.2,3590.1 5163.8,3593.9 5169,3598.4 5173.6,3603.5 5177.7,3609 5181,3615 5183.7,3621.3 5185.6,3627.9 5186.8,3634.6 5187.2,3641.5 5186.8,3648.3 5185.6,3655.1 5183.7,3661.6 5181,3668 5177.7,3673.9 5173.6,3679.5 5169,3684.5 5163.8,3689 5158.2,3692.9 5152.1,3696.1 5145.7,3698.6 5139.1,3700.3 5132.3,3701.3 5125.4,3701.5 5118.6,3700.9 5111.9,3699.5 5105.4,3697.4 5099.1,3694.6 5093.3,3691 5087.8,3686.8 5082.9,3682.1 5078.6,3676.8 5074.9,3671 5071.9,3664.8 5069.6,3658.4 5068,3651.7 5067.2,3644.9 5067.2,3638
  lines w10: 3000,4200.8 3000.4,4169.9 3001.6,4139 3003.6,4108.1 3006.4,4077.3 3009.9,4046.6 3014.3,4016 3019.5,3985.5 3025.4,3955.2 3032.1,3925 3039.6,3895 3047.9,3865.2 3056.9,3835.6 3066.7,3806.3 3077.2,3777.2 3088.5,3748.4 3100.5,3719.9 3113.2,3691.8 3126.7,3663.9 3140.9,3636.4 3155.8,3609.3 3171.3,3582.6 3187.6,3556.3 3204.5,3530.5 3222.1,3505 3240.4,3480.1 3259.2,3455.6 3278.7,3431.6 3298.8,3408.1 3319.5,3385.1 3340.8,3362.7 3362.7,3340.8 3385.1,3319.5 3408.1,3298.8 3431.6,3278.7 3455.6,3259.2 3480.1,3240.4 3505,3222.1 3530.5,3204.5 3556.3,3187.6 3582.6,3171.3 3609.3,3155.8 3636.4,3140.9 3663.9,3126.7 3691.8,3113.2 3719.9,3100.5 3748.4,3088.5 3777.2,3077.2 3806.3,3066.7 3835.6,3056.9 3865.2,3047.9 3895,3039.6 3925,3032.1 3955.2,3025.4 3985.5,3019.5 4016,3014.3 4046.6,3009.9 4077.3,3006.4 4108.1,3003.6 4139,3001.6 4169.9,3000.4 4200.8,3000 4231.7,3000.4 4262.6,3001.6 4293.5,3003.6 4324.3,3006.4 4355,3009.9 4385.6,3014.3 4416.1,3019.5 4446.4,3025.4 4476.6,3032.1 4506.6,3039.6 4536.4,3047.9 4566,3056.9 4595.3,3066.7 4624.4,3077.2 4653.2,3088.5 4681.6,3100.5 4709.8,3113.2 4737.7,3126.7 4765.1,3140.9 4792.2,3155.8 4818.9,3171.3 4845.2,3187.6 4871.1,3204.5 4896.5,3222.1 4921.5,3240.4 4946,3259.2 4970,3278.7 4993.5,3298.8 5016.5,3319.5 5038.9,3340.8 5060.7,3362.7 5082,3385.1 5102.7,3408.1 5122.8,3431.6 5142.3,3455.6 5161.2,3480.1 5179.5,3505 5197.1,3530.5 5214,3556.3 5230.2,3582.6 5245.8,3609.3 5260.7,3636.4 5274.9,3663.9 5288.3,3691.8 5301.1,3719.9 5313.1,3748.4 5324.4,3777.2 5334.9,3806.3 5344.7,3835.6 5353.7,3865.2 5362,3895 5369.5,3925 5376.2,3955.2 5382.1,3985.5 5387.3,4016 5391.6,4046.6 5395.2,4077.3 5398,4108.1 5400,4139 5401.2,4169.9 5401.6,4200.8 5401.2,4231.7 5400,4262.6 5398,4293.5 5395.2,4324.3 5391.6,4355 5387.3,4385.6 5382.1,4416.1 5376.2,4446.4 5369.5,4476.6 5362,4506.6 5353.7,4536.4 5344.7,4566 5334.9,4595.3 5324.4,4624.4 5313.1,4653.2 5301.1,4681.6 5288.3,4709.8 5274.9,4737.7 5260.7,4765.1 5245.8,4792.2 5230.2,4818.9 5214,4845.2 5197.1,4871.1 5179.5,4896.5 5161.2,4921.5 5142.3,4946 5122.8,4970 5102.7,4993.5 5082,5016.5 5060.7,5038.9 5038.9,5060.7 5016.5,5082 4993.5,5102.7 4970,5122.8 4946,5142.3 4921.5,5161.2 4896.5,5179.5 4871.1,5197.1 4845.2,5214 4818.9,5230.2 4792.2,5245.8 4765.1,5260.7 4737.7,5274.9 4709.8,5288.3 4681.6,5301.1 4653.2,5313.1 4624.4,5324.4 4595.3,5334.9 4566,5344.7 4536.4,5353.7 4506.6,5362 4476.6,5369.5 4446.4,5376.2 4416.1,5382.1 4385.6,5387.3 4355,5391.6 4324.3,5395.2 4293.5,5398 4262.6,5400 4231.7,5401.2 4200.8,5401.6 4169.9,5401.2 4139,5400 4108.1,5398 4077.3,5395.2 4046.6,5391.6 4016,5387.3 3985.5,5382.1 3955.2,5376.2 3925,5369.5 3895,5362 3865.2,5353.7 3835.6,5344.7 3806.3,5334.9 3777.2,5324.4 3748.4,5313.1 3719.9,5301.1 3691.8,5288.3 3663.9,5274.9 3636.4,5260.7 3609.3,5245.8 3582.6,5230.2 3556.3,5214 3530.5,5197.1 3505,5179.5 3480.1,5161.2 3455.6,5142.3 3431.6,5122.8 3408.1,5102.7 3385.1,5082 3362.7,5060.7 3340.8,5038.9 3319.5,5016.5 3298.8,4993.5 3278.7,4970 3259.2,4946 3240.4,4921.5 3222.1,4896.5 3204.5,4871.1 3187.6,4845.2 3171.3,4818.9 3155.8,4792.2 3140.9,4765.1 3126.7,4737.7 3113.2,4709.8 3100.5,4681.6 3088.5,4653.2 3077.2,4624.4 3066.7,4595.3 3056.9,4566 3047.9,4536.4 3039.6,4506.6 3032.1,4476.6 3025.4,4446.4 3019.5,4416.1 3014.3,4385.6 3009.9,4355 3006.4,4324.3 3003.6,4293.5 3001.6,4262.6 3000.4,4231.7 3000,4200.8

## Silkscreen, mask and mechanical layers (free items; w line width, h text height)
Top Silkscreen Layer:
  drawing of 308 lines, arcs and shapes, not listed
  text "WYVERN-E r7.4" at 3676.5,5150.3 h98.4
Bottom Silkscreen Layer:
  drawing of 308 lines, arcs and shapes, not listed
  text "WYVERN-E r7.4" at 4623.8,5146.9 h118.1
Mechanical Layer:
  drawing of 220 lines, arcs and shapes, not listed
